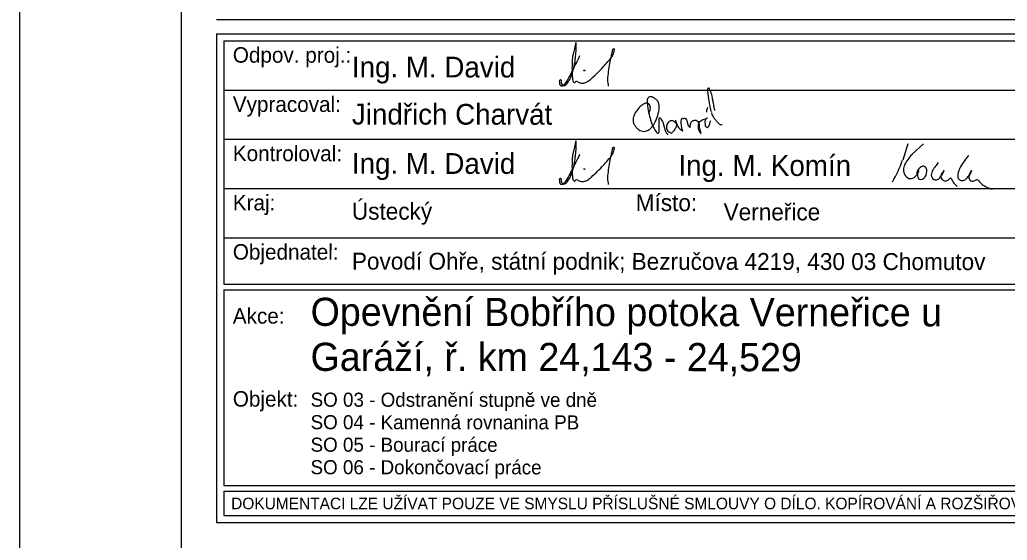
# Model space of a CAD drawing. Extents: x 67.3 to 115.4, y -93.9 to -78.3.
# Drawn here: x 104.8 to 111.82, y -86.38 to -82.68 of the extents above; entities that cross this region are included whole.
import ezdxf

# ---------------------------------------------------------------- set-up
doc = ezdxf.new("R2010")
doc.units = 0
for name, color, linetype in [('07_rozpiska', 7, 'Continuous'), ('07_rámeček', 7, 'Continuous'), ('Default', 7, 'Continuous'), ('Rozpiska + rámeček', 7, 'Continuous')]:
    doc.layers.add(name, color=color, linetype=linetype)

# ---------------------------------------------------------------- blocks, each defined once
blk = doc.blocks.new('Charvat')
at = {"layer": 'Rozpiska + rámeček'}
for points in [[(0.0826, 0.02), (0.0817, 0.0228), (0.0806, 0.0281), (0.0796, 0.0345), (0.0789, 0.0395), (0.0784, 0.0445), (0.0784, 0.0456), (0.0785, 0.0469), (0.0787, 0.0476), (0.0791, 0.0473), (0.0804, 0.0456), (0.0816, 0.0427), (0.0827, 0.0394), (0.0832, 0.0363), (0.0841, 0.0314), (0.0846, 0.0282), (0.0855, 0.0238), (0.086, 0.0216)], [(0.0108, 0.0178), (0.0123, 0.0208), (0.0129, 0.0234), (0.0122, 0.0279), (0.0108, 0.0294), (0.0087, 0.0301), (0.0059, 0.0293), (0.0024, 0.0271), (-0.0017, 0.0225), (-0.0049, 0.0177), (-0.0062, 0.0145), (-0.0067, 0.0115), (-0.0063, 0.0075), (-0.0059, 0.0064), (-0.0039, 0.0034), (-0.0014, 0.0007), (0.001, -0.001), (0.0043, -0.0019), (0.0075, -0.0019), (0.0097, -0.001), (0.0131, 0.0013), (0.0158, 0.0045), (0.0192, 0.0101), (0.022, 0.0182), (0.0223, 0.0193), (0.023, 0.0256), (0.0227, 0.0293), (0.0219, 0.0315), (0.0199, 0.034), (0.017, 0.036), (0.0147, 0.0371), (0.0142, 0.0372), (0.013, 0.0373), (0.0113, 0.0368), (0.0106, 0.0362), (0.0097, 0.0348), (0.0095, 0.0343), (0.0093, 0.0333), (0.0093, 0.0314), (0.0096, 0.0279), (0.0105, 0.0221), (0.012, 0.0151), (0.0133, 0.0108), (0.0166, 0.0023), (0.0195, -0.0026), (0.0202, -0.0035), (0.0214, -0.0042), (0.022, -0.0042), (0.0225, -0.0034), (0.023, -0.0014), (0.0231, 0), (0.0231, 0.0051), (0.0231, 0.0111), (0.0231, 0.0124), (0.0233, 0.0132), (0.0236, 0.0135), (0.024, 0.0133), (0.0254, 0.0115), (0.0268, 0.0092), (0.0279, 0.0059), (0.0289, 0.0018), (0.0298, -0.0012), (0.0315, -0.0041), (0.0327, -0.0059)], [(0.0771, 0.0198), (0.0779, 0.024), (0.0784, 0.0252)], [(0.0428, 0.0062), (0.0417, 0.0075), (0.0401, 0.009), (0.0394, 0.0095), (0.0378, 0.0101), (0.0368, 0.0101), (0.0353, 0.0098), (0.034, 0.0088), (0.0326, 0.0071), (0.0316, 0.0051), (0.0313, 0.0026), (0.0313, 0.0011), (0.0322, -0.0007), (0.0338, -0.0025), (0.0354, -0.0034), (0.0366, -0.0037), (0.0381, -0.0031), (0.0397, -0.0014), (0.0411, 0.0004), (0.0422, 0.0025), (0.043, 0.005), (0.043, 0.0063), (0.0429, 0.0069), (0.0424, 0.0086), (0.0414, 0.0106), (0.0421, 0.009), (0.0433, 0.0053), (0.0444, 0.0034), (0.0458, 0.0017), (0.0476, 0), (0.0497, -0.0015), (0.0498, -0.0016), (0.0499, -0.0016), (0.0499, -0.0014), (0.0492, 0.0003), (0.0487, 0.0022), (0.0482, 0.0055), (0.048, 0.0086), (0.0484, 0.0114), (0.0491, 0.0131), (0.0493, 0.013), (0.0506, 0.0127), (0.0522, 0.0131), (0.0539, 0.0111), (0.0547, 0.0094), (0.0552, 0.0074), (0.0556, 0.0056), (0.0566, 0.0038), (0.058, 0.0025), (0.0582, 0.0031), (0.0585, 0.0057), (0.0589, 0.0076), (0.0593, 0.0083), (0.0604, 0.0095), (0.0616, 0.0102), (0.0632, 0.0106), (0.065, 0.0106), (0.0665, 0.0094), (0.0678, 0.0078), (0.0686, 0.0033), (0.0691, 0.0001), (0.0701, -0.0031), (0.0705, -0.0044), (0.0697, -0.0035), (0.0682, -0.0005), (0.0677, 0.0025), (0.0677, 0.0059), (0.0683, 0.0079), (0.0702, 0.01), (0.0728, 0.0114), (0.0756, 0.0122), (0.0781, 0.0133), (0.0764, 0.0125), (0.0755, 0.0112), (0.0751, 0.0096), (0.0751, 0.0075), (0.0753, 0.005), (0.0753, 0.0048), (0.0758, 0.0038), (0.0766, 0.003), (0.0772, 0.0026), (0.0776, 0.0025), (0.0783, 0.0027), (0.0791, 0.0034), (0.0799, 0.0047), (0.0806, 0.0069), (0.0816, 0.0104)], [(0.0947, 0.0053), (0.0934, 0.0053), (0.0921, 0.0059), (0.0901, 0.0076), (0.0883, 0.0095), (0.0858, 0.0127), (0.0839, 0.0159), (0.0829, 0.0186), (0.0827, 0.0193)]]:
    blk.add_spline(points, degree=3, dxfattribs=at)

msp = doc.modelspace()

# ---------------------------------------------------------------- linework, layer by layer
at = {"layer": '07_rozpiska'}
msp.add_line((114.7958, -82.6813), (106.1958, -82.6813), dxfattribs=at)
for points in [[(108.7509, -82.8729), (108.7522, -82.8631), (108.7515, -82.8434), (108.7437, -82.8742), (108.7334, -82.9163), (108.7272, -82.9425), (108.724, -82.9862), (108.7224, -83.0219), (108.7256, -83.0964), (108.7288, -83.1161), (108.7415, -83.1278), (108.746, -83.1246), (108.747, -83.1223), (108.7541, -83.1174), (108.7667, -83.1239), (108.7804, -83.1294), (108.7953, -83.132), (108.8134, -83.1291), (108.8338, -83.1207), (108.8604, -83.0993), (108.9041, -83.0582), (108.9443, -83.017), (108.9783, -82.9785), (109.0058, -82.9451), (109.0207, -82.9121), (109.0243, -82.8959), (109.023, -82.8891), (109.0168, -82.8904), (109.0061, -82.9137), (109.0003, -82.9376), (108.9916, -82.9794), (108.9828, -83.0351), (108.9757, -83.0912), (108.975, -83.12), (108.9786, -83.1417), (108.9805, -83.1524)], [(108.7447, -82.9781), (108.7467, -82.9522), (108.7493, -82.9296), (108.7512, -82.9053), (108.7509, -82.8729)], [(108.6362, -83.1333), (108.6343, -83.1216), (108.6352, -83.1139), (108.6401, -83.1074), (108.6437, -83.1067), (108.6456, -83.1187), (108.6462, -83.133), (108.6543, -83.1453), (108.6657, -83.1495), (108.6764, -83.1456), (108.6858, -83.1378), (108.6909, -83.131), (108.7062, -83.1067), (108.7123, -83.0951), (108.7282, -83.0488), (108.7447, -82.9781)], [(108.7771, -82.9386), (108.7496, -82.9934), (108.7033, -83.0854), (108.6699, -83.1398), (108.6576, -83.1511), (108.6482, -83.1527), (108.6424, -83.1521), (108.6381, -83.1453), (108.6362, -83.1333)], [(108.8095, -83.0403), (108.8072, -83.0413), (108.8072, -83.0433), (108.8089, -83.0442), (108.8121, -83.0449), (108.8127, -83.0433), (108.8127, -83.0416), (108.8095, -83.0403)], [(108.7509, -83.5729), (108.7522, -83.5631), (108.7515, -83.5434), (108.7437, -83.5742), (108.7334, -83.6163), (108.7272, -83.6425), (108.724, -83.6862), (108.7224, -83.7219), (108.7256, -83.7964), (108.7288, -83.8161), (108.7415, -83.8278), (108.746, -83.8246), (108.747, -83.8223), (108.7541, -83.8174), (108.7667, -83.8239), (108.7804, -83.8294), (108.7953, -83.832), (108.8134, -83.8291), (108.8338, -83.8207), (108.8604, -83.7993), (108.9041, -83.7582), (108.9443, -83.717), (108.9783, -83.6785), (109.0058, -83.6451), (109.0207, -83.6121), (109.0243, -83.5959), (109.023, -83.5891), (109.0168, -83.5904), (109.0061, -83.6137), (109.0003, -83.6376), (108.9916, -83.6794), (108.9828, -83.7351), (108.9757, -83.7912), (108.975, -83.82), (108.9786, -83.8417), (108.9805, -83.8524)], [(108.7447, -83.6781), (108.7467, -83.6522), (108.7493, -83.6296), (108.7512, -83.6053), (108.7509, -83.5729)], [(108.6362, -83.8333), (108.6343, -83.8216), (108.6352, -83.8139), (108.6401, -83.8074), (108.6437, -83.8067), (108.6456, -83.8187), (108.6462, -83.833), (108.6543, -83.8453), (108.6657, -83.8495), (108.6764, -83.8456), (108.6858, -83.8378), (108.6909, -83.831), (108.7062, -83.8067), (108.7123, -83.7951), (108.7282, -83.7488), (108.7447, -83.6781)], [(108.7771, -83.6386), (108.7496, -83.6934), (108.7033, -83.7854), (108.6699, -83.8398), (108.6576, -83.8511), (108.6482, -83.8527), (108.6424, -83.8521), (108.6381, -83.8453), (108.6362, -83.8333)], [(108.8095, -83.7403), (108.8072, -83.7413), (108.8072, -83.7433), (108.8089, -83.7442), (108.8121, -83.7449), (108.8127, -83.7433), (108.8127, -83.7416), (108.8095, -83.7403)]]:
    msp.add_spline(points, degree=3, dxfattribs=at)
at = {"layer": 'Default'}
for p, q in [((111.1756, -83.7799), (111.19, -83.754)), ((111.4175, -83.8087), (111.4276, -83.826)), ((111.4492, -83.8548), (111.4607, -83.8663))]:
    msp.add_line(p, q, dxfattribs=at)
for points in [[(111.1108, -83.5639), (111.0748, -83.6791)], [(111.2231, -83.5639), (111.1396, -83.6388)], [(111.3268, -83.6964), (111.3167, -83.7108)], [(111.5428, -83.646), (111.514, -83.682)], [(111.298, -83.7367), (111.2951, -83.7396)], [(111.3628, -83.7655), (111.37, -83.754), (111.3599, -83.7655)], [(111.5399, -83.7972), (111.5644, -83.754), (111.5543, -83.7799)], [(111.3455, -83.7972), (111.3455, -83.7972)], [(111.3484, -83.7799), (111.3484, -83.7828)]]:
    msp.add_lwpolyline(points, dxfattribs=at)
for centre, radius, start, end in [((110.1415, -83.3324), 0.9948, 329.80858, 339.56815), ((111.3996, -83.8806), 0.3545, 137.00062, 151.51062), ((111.7457, -83.8677), 0.2956, 141.11668, 151.43002), ((111.152, -83.7472), 0.0732, 150.83631, 201.23374), ((111.2528, -83.7954), 0.084, 133.12102, 160.6603), ((111.232, -83.7877), 0.0529, 142.82783, 193.29225), ((111.3837, -83.8022), 0.1085, 146.31446, 165.71836), ((111.0538, -83.5822), 0.288, 326.31446, 326.46946), ((111.5385, -83.8936), 0.288, 140.57196, 146.46893), ((111.1949, -83.6865), 0.1862, 320.58833, 335.16259), ((111.4014, -83.804), 0.0576, 139.19606, 154.94016), ((111.5266, -83.7884), 0.0617, 158.78845, 195.14726), ((111.6674, -83.8271), 0.2075, 150.931, 162.8917), ((111.1585, -83.7376), 0.083, 205.78195, 234.22418), ((111.1301, -83.774), 0.0369, 236.98468, 294.62862), ((111.17, -83.8912), 0.0864, 108.04736, 108.08265), ((111.1076, -83.7298), 0.0864, 295.93387, 323.63221), ((111.3104, -83.7872), 0.0323, 245.35778, 276.92267), ((111.3034, -83.7731), 0.0475, 283.31943, 318.16716), ((111.3742, -83.7942), 0.0288, 154.94151, 187.17365), ((111.3742, -83.7955), 0.0286, 186.45097, 212.31824), ((111.3775, -83.7936), 0.0324, 212.08411, 258.70933), ((111.3791, -83.79), 0.0362, 257.35338, 296.27075), ((111.3728, -83.7858), 0.043, 301.37529, 327.02531), ((111.4138, -83.8121), 0.00576, 26.63136, 150.41952), ((111.5051, -83.7885), 0.0864, 206.63144, 229.82938), ((111.4923, -83.7965), 0.0265, 197.61582, 249.38851), ((111.4988, -83.7778), 0.0463, 250.12564, 275.82035), ((111.4994, -83.789), 0.035, 276.59581, 304.89281), ((111.4576, -83.7405), 0.099, 308.6573, 325.5075), ((111.5748, -83.8029), 0.0297, 172.16185, 218.17447), ((111.6118, -83.8117), 0.0677, 151.17648, 169.00349), ((111.5739, -83.7945), 0.0349, 229.93747, 256.22885), ((111.5701, -83.7829), 0.0458, 264.36538, 302.31991), ((111.6017, -83.8331), 0.0136, 38.96313, 121.674), ((111.7211, -83.7484), 0.1329, 214.99845, 231.36881), ((111.7576, -83.6828), 0.2073, 234.79421, 256.99308)]:
    msp.add_arc(centre, radius, start, end, dxfattribs=at)
for centre, major_axis, ratio, start_param, end_param in [((111.2115, -83.7696), (0.0152, 0.0459), 0.677007, 2.488228, 7.220838), ((111.3143, -83.7863), (-0.0357, 0.0109), 0.932374, 0, 1.363098)]:
    msp.add_ellipse(centre, major_axis=major_axis, ratio=ratio, start_param=start_param, end_param=end_param, dxfattribs=at)
at = {"layer": 'Rozpiska + rámeček'}
for p, q in [((106.1958, -82.7813), (106.1958, -86.2563)), ((106.1958, -82.7813), (114.7958, -82.7813)), ((106.2458, -82.8313), (106.2458, -84.5613)), ((106.2458, -82.8313), (111.9058, -82.8313)), ((106.2458, -83.1813), (111.9058, -83.1813)), ((106.2458, -83.5313), (111.9058, -83.5313)), ((106.2458, -83.8813), (111.9058, -83.8813)), ((106.2458, -84.2313), (111.9058, -84.2313)), ((106.2458, -84.5613), (111.9058, -84.5613)), ((106.2458, -84.6013), (111.9058, -84.6013)), ((106.2458, -84.6013), (106.2458, -85.9913)), ((106.2458, -85.9913), (111.9058, -85.9913)), ((106.2458, -86.0313), (114.7458, -86.0313)), ((106.2458, -86.0313), (106.2458, -86.2063)), ((106.2458, -86.2063), (114.7458, -86.2063)), ((106.1958, -86.2563), (114.7958, -86.2563))]:
    msp.add_line(p, q, dxfattribs=at)
for points in [[(104.7958, -79.0813), (115.2958, -79.0813), (115.2958, -93.9313), (104.7958, -93.9313)], [(105.9458, -79.0813), (115.0458, -79.0813), (115.0458, -86.5063), (105.9458, -86.5063)]]:
    msp.add_lwpolyline(points, close=True, dxfattribs=at)

# ---------------------------------------------------------------- block references
at = {"layer": '07_rámeček', "xscale": 6.250000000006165, "yscale": 6.250000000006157, "rotation": 3.739011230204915e-09}
msp.add_blockref('Charvat', (109.1988, -83.462), dxfattribs=at)

# ---------------------------------------------------------------- texts
at = {"layer": '07_rozpiska'}
for s, height, p in [('Opevnění Bobřího potoka Verneřice u ', 0.2, (106.8638, -84.8572)), ('Garáží, ř. km 24,143 - 24,529', 0.2, (106.8636, -85.1772)), ('SO 03 - Odstranění stupně ve dně', 0.1, (106.8639, -85.4319)), ('SO 04 - Kamenná rovnanina PB', 0.1, (106.8638, -85.5919)), ('SO 05 - Bourací práce', 0.1, (106.8636, -85.7519)), ('SO 06 - Dokončovací práce', 0.1, (106.8635, -85.9119))]:
    msp.add_text(s, height=height, rotation=359.95393, dxfattribs=at).set_placement(p)
at = {"layer": 'Rozpiska + rámeček'}
for s, height, rotation, p in [('Odpov. proj.:', 0.11, 359.95393, (106.3108, -82.9863)), ('Ing. M. David', 0.147465, 359.95278, (107.1575, -83.0907)), ('Vypracoval:', 0.11, 359.95393, (106.3108, -83.3363)), ('Jindřich Charvát', 0.147465, 359.95278, (107.1575, -83.4263)), ('Kontroloval:', 0.11, 359.95393, (106.3108, -83.6863)), ('Ing. M. David', 0.147465, 359.95278, (107.1575, -83.7763)), ('Ing. M. Komín', 0.147465, 359.95278, (109.4792, -83.7907)), ('Kraj:', 0.11, 359.95393, (106.3108, -84.0363)), ('Ústecký', 0.12, 359.95393, (107.1575, -84.1023)), ('Místo:', 0.12, 359.95393, (109.1758, -84.0413)), ('Verneřice', 0.12, 359.95278, (109.8008, -84.1071)), ('Objednatel:', 0.11, 359.95393, (106.3108, -84.3863)), ('Povodí Ohře, státní podnik; Bezručova 4219, 430 03 Chomutov', 0.12, 359.95278, (107.1575, -84.4571)), ('Akce:', 0.11, 359.95393, (106.3108, -84.8413)), ('Objekt:', 0.11, 359.95393, (106.3108, -85.4314))]:
    msp.add_text(s, height=height, rotation=rotation, dxfattribs=at).set_placement(p)
msp.add_text('DOKUMENTACI LZE UŽÍVAT POUZE VE SMYSLU PŘÍSLUŠNÉ SMLOUVY O DÍLO. KOPÍROVÁNÍ A ROZŠIŘOVÁNÍ POUZE PO PŘEDCHOZÍM SOUHLASU  AZ CONSULT spol. s. r.o.', height=0.0822563, dxfattribs=at).set_placement((106.2988, -86.1609))

doc.saveas('drawing.dxf')
